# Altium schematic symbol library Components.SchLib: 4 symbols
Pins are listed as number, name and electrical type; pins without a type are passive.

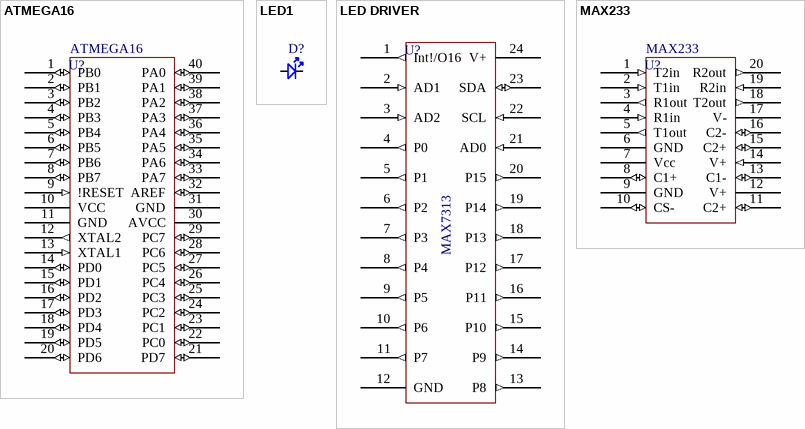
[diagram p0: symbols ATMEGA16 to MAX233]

## ATMEGA16
designator U?
footprint DIP-40
pins: 1 PB0 (io) "(XCK/T0)", 2 PB1 (io) "(T1)", 3 PB2 (io) "(INT2/AIN0)", 4 PB3 (io) "(OC0/AIN1)", 5 PB4 (io) "(!SS)", 6 PB5 (io) "(MOSI)", 7 PB6 (io) "(MISO)", 8 PB7 (io) "(SCK)", 9 !RESET (in), 10 VCC (power), 11 GND (power), 12 XTAL2 (out), 13 XTAL1 (in), 14 PD0 (io) "(RXD)", 15 PD1 (io) "(TXD)", 16 PD2 (io) "(INT0)", 17 PD3 (io) "(INT1)", 18 PD4 (io) "(OC1B)", 19 PD5 (io) "(OC1A)", 20 PD6 (io) "(ICP1)", 21 PD7 (io) "(OC2)", 22 PC0 (io) "(SCL)", 23 PC1 (io) "(SDA)", 24 PC2 (io) "(TCK)", 25 PC3 (io) "(TMS)", 26 PC4 (io) "(TDO)", 27 PC5 (io) "(TDI)", 28 PC6 (io) "(TOSC1)", 29 PC7 (io) "(TOSC2)", 30 AVCC (power), 31 GND (power), 32 AREF (io), 33 PA7 (io) "(ADC7)", 34 PA6 (io) "(ADC6)", 35 PA5 (io) "(ADC5)", 36 PA4 (io) "(ADC4)", 37 PA3 (io) "(ADC3)", 38 PA2 (io) "(ADC2)", 39 PA1 (io) "(ADC1)", 40 PA0 (io) "(ADC0)"

## LED1
designator D?, comment LED  (value not drawn)
Typical RED GaAs LED; Manufacturer: Generic Components; Class I: Optoelectronic
footprint LED-1 (Footprint not found)
simulation model LED1 (Diode)
pins: 1 A (power), 2 K (power)

## LED DRIVER
designator U?, comment MAX7313
footprint SSO-G24/C6.8
pins: 1 Int!/O16 (out), 2 AD1 (in), 3 AD2 (in), 4 P0 (out), 5 P1 (out), 6 P2 (out), 7 P3 (out), 8 P4 (out), 9 P5 (out), 10 P6 (out), 11 P7 (out), 12 GND (power), 13 P8 (out), 14 P9 (out), 15 P10 (out), 16 P11 (out), 17 P12 (out), 18 P13 (out), 19 P14 (out), 20 P15 (out), 21 AD0 (in), 22 SCL (in), 23 SDA (io), 24 V+ (power)

## MAX233
designator U?
footprint DIP-20/E5.3 (Footprint not found)
pins: 1 T2in (in), 2 T1in (in), 3 R1out (out), 4 R1in (in), 5 T1out (out), 6 GND (power), 7 Vcc (power), 8 C1+ (io) "(V+)", 9 GND (power), 10 CS- (io) "(V-)", 11 C2+ (io) "(C2-)", 12 V+ (power) "(C2+)", 13 C1- (io) "(C1+)", 14 V+ (in) "(C1-)", 15 C2+ (io), 16 C2- (io), 17 V- (power), 18 T2out (out), 19 R2in (in), 20 R2out (out)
